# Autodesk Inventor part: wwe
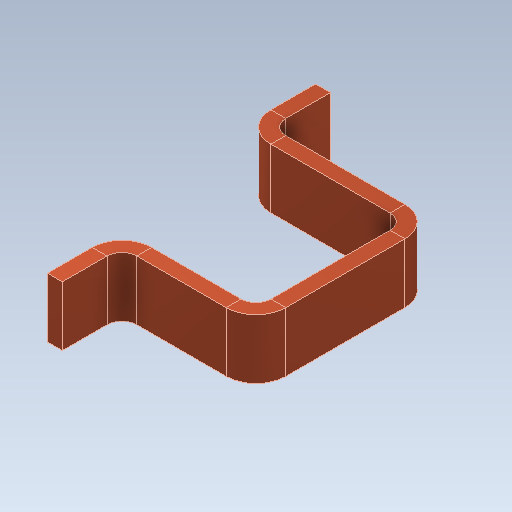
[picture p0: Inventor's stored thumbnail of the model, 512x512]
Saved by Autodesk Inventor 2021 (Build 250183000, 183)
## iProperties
Created: 2021-07
Part Number: wwe
Material: Copper, Wrought
Document SubType Name: Sheet Metal
Designer: user
Density: 8.94 g/cm^3
Sheet Metal Rule: Default_mm
Appearance: Copper - Satin
Author: user
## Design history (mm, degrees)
node "Face1"
  sketch "Sketch1"
    geometry: L1 (0, 0)-(5, 0); L2 (5, 0)-(5, 2); L3 (5, 2)-(0, 2); L4 (0, 2)-(0, 0)
    constraints: 8 end point, 2 parallel, 1 horizontal, 1 perpendicular
    dimensions: "d0" = 5 distance of L3.end L2.end; "d1" = 2 distance of L2.end L1.end
node "Flange1"
node "Flange2"
node "Flange3"
body "Solid1"
face "Plate1" dims "d2" = 0.5 (= Thickness)
sketch "Sketch2"
  geometry: L1 through (-1, 0) direction (1, 0); L2 through (0, 2) direction (0, 1); L3 (0, 4)-(-2, 4); L4 (-2, 4)-(-2, 0)
  constraints: 6 end point, 1 horizontal, 1 perpendicular, 1 vertical
face "Plate2" dims "d2" = 0.5 (= Thickness), "d3" = 0.5 (= BendReliefWidth), "d4" = 0.25 (= BendReliefDepth), "d5" = 1 (= MinimumRemnant), "d6" = 0.5 (= TransitionRadius), "d7" = 5, "d8" = 90 deg, "d9" = 0.5 (= BendRadius), "d10" = 2 (= CornerReliefSize), "d11" = 0.5 (= GapSize), "d12" = 0.5 (= JacobiRadiusSize), "SeamGap" = 0.01
bend "Bend1" dims "d2" = 0.5 (= Thickness), "d3" = 0.5 (= BendReliefWidth), "d4" = 0.25 (= BendReliefDepth), "d5" = 1 (= MinimumRemnant), "d6" = 0.5 (= TransitionRadius), "d7" = 5, "d8" = 90 deg, "d9" = 0.5 (= BendRadius), "SeamGap" = 0.01
feature "Corner1" dims "d7" = 5, "d8" = 90 deg, "d10" = 2 (= CornerReliefSize), "d11" = 0.5 (= GapSize), "d12" = 0.5 (= JacobiRadiusSize)
sketch "Sketch3"
  geometry: L1 through (0, -1) direction (0, 1); L2 through (-2, 0) direction (-1, -1.38e-33); L3 (-4, 0)-(-4, -2); L4 (-4, -2)-(0, -2)
  constraints: 6 end point, 1 horizontal, 1 perpendicular, 1 vertical
face "Plate3" dims "d2" = 0.5 (= Thickness), "d13" = 0.5 (= BendReliefWidth), "d14" = 0.25 (= BendReliefDepth), "d15" = 1 (= MinimumRemnant), "d16" = 0.5 (= TransitionRadius), "d17" = 5, "d18" = 90 deg, "d19" = 0.5 (= BendRadius), "d20" = 2 (= CornerReliefSize), "d21" = 0.5 (= GapSize), "d22" = 0.5 (= JacobiRadiusSize), "SeamGap" = 0.01
bend "Bend2" dims "d2" = 0.5 (= Thickness), "d13" = 0.5 (= BendReliefWidth), "d14" = 0.25 (= BendReliefDepth), "d15" = 1 (= MinimumRemnant), "d16" = 0.5 (= TransitionRadius), "d17" = 5, "d18" = 90 deg, "d19" = 0.5 (= BendRadius), "SeamGap" = 0.01
feature "Corner2" dims "d17" = 5, "d18" = 90 deg, "d20" = 2 (= CornerReliefSize), "d21" = 0.5 (= GapSize), "d22" = 0.5 (= JacobiRadiusSize)
sketch "Sketch4"
  geometry: L1 through (-1, 0) direction (1, -5.41e-33); L2 through (0, 1.25) direction (-7.41e-18, 1); L3 (0, 2.5)-(-2, 2.5); L4 (-2, 2.5)-(-2, 0)
  constraints: 6 end point, 1 horizontal, 1 perpendicular, 1 vertical
face "Plate4" dims "d2" = 0.5 (= Thickness), "d23" = 0.5 (= BendReliefWidth), "d24" = 0.25 (= BendReliefDepth), "d25" = 1 (= MinimumRemnant), "d26" = 0.5 (= TransitionRadius), "d27" = 2.5, "d28" = 90 deg, "d29" = 0.5 (= BendRadius), "d30" = 2 (= CornerReliefSize), "d31" = 0.5 (= GapSize), "d32" = 0.5 (= JacobiRadiusSize), "SeamGap" = 0.01
bend "Bend3" dims "d2" = 0.5 (= Thickness), "d23" = 0.5 (= BendReliefWidth), "d24" = 0.25 (= BendReliefDepth), "d25" = 1 (= MinimumRemnant), "d26" = 0.5 (= TransitionRadius), "d27" = 2.5, "d28" = 90 deg, "d29" = 0.5 (= BendRadius), "SeamGap" = 0.01
feature "Corner3" dims "d27" = 2.5, "d28" = 90 deg, "d30" = 2 (= CornerReliefSize), "d31" = 0.5 (= GapSize), "d32" = 0.5 (= JacobiRadiusSize)
other parameters: "Thickness" = 0.5, "BendRadius" = 0.5 (= Thickness), "BendReliefWidth" = 0.5 (= Thickness), "BendReliefDepth" = 0.25 (= 0.5 x Thickness), "CornerReliefSize" = 2 (= 4 x Thickness), "MinimumRemnant" = 1 (= 2 x Thickness), "TransitionRadius" = 0.5 (= BendRadius), "JacobiRadiusSize" = 0.5 (= BendRadius), "GapSize" = 0.5 (= Thickness)
